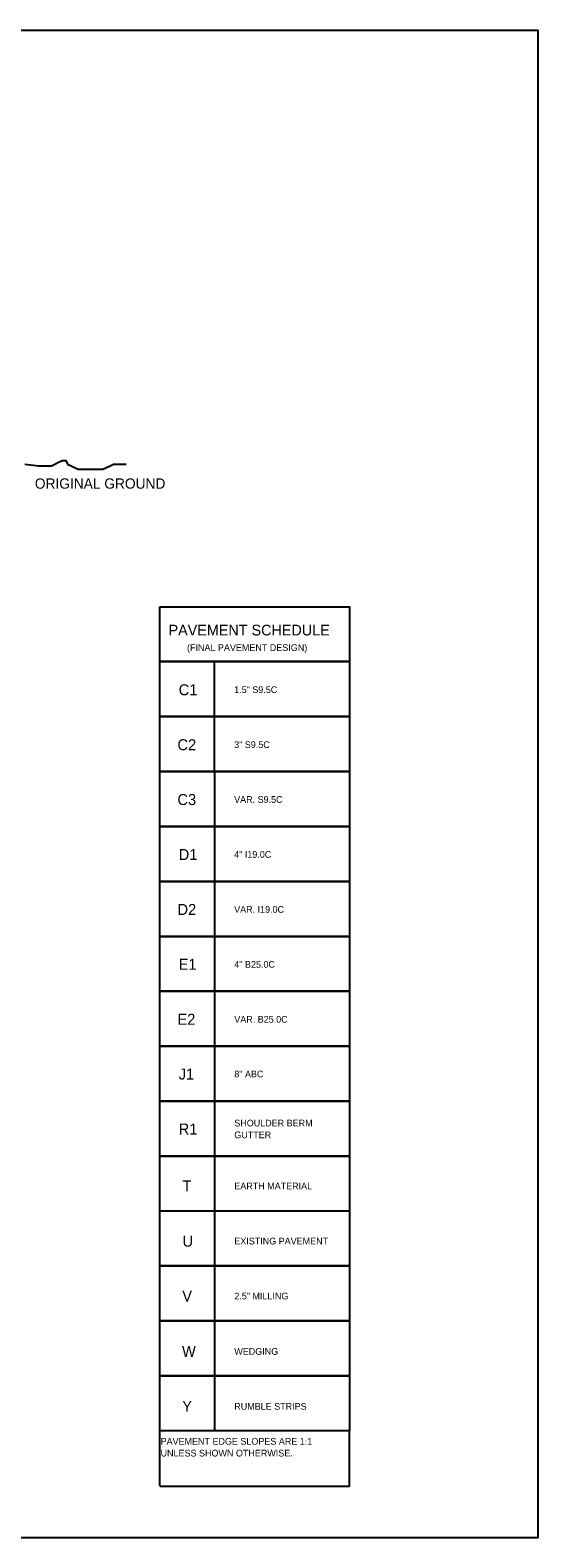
# Model space of a CAD drawing. Extents: x 1548135 to 1549339, y 868664 to 869085.
# Drawn here: x 1548268 to 1548305, y 868801.8 to 868911.8 of the extents above; entities that cross this region are included whole.
import ezdxf

# ---------------------------------------------------------------- set-up
doc = ezdxf.new("R2010")
doc.units = 0
for name, color, linetype in [('Default', 7, 'Continuous'), ('Prop Dimension', 7, 'Continuous'), ('Sheet_Data_Field_CELL', 7, 'Continuous'), ('Typical Hinge Slope Interstate CELL', 7, 'Continuous')]:
    doc.layers.add(name, color=color, linetype=linetype)

msp = doc.modelspace()

# ---------------------------------------------------------------- linework, layer by layer
at = {"layer": 'Default'}
msp.add_lwpolyline([(1548135.05, 868911.82), (1548305.05, 868911.82), (1548305.05, 868801.82), (1548135.05, 868801.82)], close=True, dxfattribs=at)
at = {"layer": 'Prop Dimension'}
msp.add_lwpolyline([(1548267.6, 868880.17), (1548268.63, 868880.04), (1548268.89, 868880.04), (1548269.28, 868880.04), (1548269.54, 868880.04), (1548269.8, 868880.17), (1548270.06, 868880.3), (1548270.32, 868880.43), (1548270.58, 868880.43), (1548270.71, 868880.17), (1548270.97, 868880.04), (1548271.23, 868879.91), (1548271.49, 868879.79), (1548271.75, 868879.79), (1548272.01, 868879.79), (1548272.27, 868879.79), (1548272.53, 868879.79), (1548272.78, 868879.79), (1548273.04, 868879.79), (1548273.3, 868879.79), (1548273.56, 868879.91), (1548273.82, 868880.04), (1548274.08, 868880.17), (1548274.47, 868880.17), (1548274.73, 868880.17), (1548274.99, 868880.17)], dxfattribs=at)
at = {"layer": 'Typical Hinge Slope Interstate CELL'}
for p, q in [((1548273.7, 868811.24), (1548273.7, 868811.24)), ((1548277.45, 868806.56), (1548277.45, 868809.66)), ((1548277.45, 868805.61), (1548277.45, 868809.62)), ((1548291.3, 868805.57), (1548291.3, 868809.62)), ((1548281.46, 868805.57), (1548277.45, 868805.57)), ((1548291.3, 868805.57), (1548281.46, 868805.57))]:
    msp.add_line(p, q, dxfattribs=at)
msp.add_lwpolyline([(1548277.45, 868869.75), (1548291.29, 868869.75), (1548291.29, 868865.75), (1548277.45, 868865.75)], close=True, dxfattribs=at)
for points in [[(1548281.45, 868861.74), (1548277.45, 868861.74), (1548277.45, 868865.75), (1548291.29, 868865.75), (1548291.29, 868861.74), (1548281.45, 868861.74), (1548281.45, 868865.75)], [(1548281.45, 868857.73), (1548277.45, 868857.73), (1548277.45, 868861.74), (1548291.29, 868861.74), (1548291.29, 868857.73), (1548281.45, 868857.73), (1548281.45, 868861.74)], [(1548281.46, 868853.72), (1548277.45, 868853.72), (1548277.45, 868857.73), (1548291.29, 868857.73), (1548291.29, 868853.72), (1548281.46, 868853.72), (1548281.46, 868857.73)], [(1548281.46, 868849.71), (1548277.45, 868849.71), (1548277.45, 868853.72), (1548291.29, 868853.72), (1548291.29, 868849.71), (1548281.46, 868849.71), (1548281.46, 868853.72)], [(1548281.46, 868845.7), (1548277.45, 868845.7), (1548277.45, 868849.71), (1548291.29, 868849.71), (1548291.29, 868845.7), (1548281.46, 868845.7), (1548281.46, 868849.71)], [(1548281.46, 868841.7), (1548277.45, 868841.7), (1548277.45, 868845.71), (1548291.3, 868845.71), (1548291.3, 868841.7), (1548281.46, 868841.7), (1548281.46, 868845.71)], [(1548281.46, 868841.69), (1548277.45, 868841.69), (1548277.45, 868845.7), (1548291.29, 868845.7), (1548291.29, 868841.69), (1548281.46, 868841.69), (1548281.46, 868845.7)], [(1548281.46, 868837.69), (1548277.45, 868837.69), (1548277.45, 868841.7), (1548291.3, 868841.7), (1548291.3, 868837.69), (1548281.46, 868837.69), (1548281.46, 868841.7)], [(1548281.46, 868833.69), (1548277.45, 868833.69), (1548277.45, 868837.7), (1548291.3, 868837.7), (1548291.3, 868833.69), (1548281.46, 868833.69), (1548281.46, 868837.7)], [(1548281.46, 868833.69), (1548277.45, 868833.69), (1548277.45, 868837.7), (1548291.3, 868837.7), (1548291.3, 868833.69), (1548281.46, 868833.69), (1548281.46, 868837.7)], [(1548281.46, 868829.68), (1548277.45, 868829.68), (1548277.45, 868833.69), (1548291.3, 868833.69), (1548291.3, 868829.68), (1548281.46, 868829.68), (1548281.46, 868833.69)], [(1548281.46, 868825.67), (1548277.45, 868825.67), (1548277.45, 868829.68), (1548291.3, 868829.68), (1548291.3, 868825.67), (1548281.46, 868825.67), (1548281.46, 868829.68)], [(1548281.46, 868821.67), (1548277.45, 868821.67), (1548277.45, 868825.68), (1548291.3, 868825.68), (1548291.3, 868821.67), (1548281.46, 868821.67), (1548281.46, 868825.68)], [(1548281.46, 868817.66), (1548277.45, 868817.66), (1548277.45, 868821.67), (1548291.3, 868821.67), (1548291.3, 868817.66), (1548281.46, 868817.66), (1548281.46, 868821.67)], [(1548281.46, 868813.65), (1548277.45, 868813.65), (1548277.45, 868817.66), (1548291.3, 868817.66), (1548291.3, 868813.65), (1548281.46, 868813.65), (1548281.46, 868817.66)], [(1548281.46, 868809.64), (1548277.45, 868809.64), (1548277.45, 868813.65), (1548291.3, 868813.65), (1548291.3, 868809.64), (1548281.46, 868809.64), (1548281.46, 868813.65)]]:
    msp.add_lwpolyline(points, dxfattribs=at)

# ---------------------------------------------------------------- texts
at = {"layer": 'Sheet_Data_Field_CELL'}
msp.add_text('ORIGINAL GROUND', height=0.75, dxfattribs=at).set_placement((1548268.33, 868878.37))
at = {"layer": 'Typical Hinge Slope Interstate CELL'}
for s, height, p in [('PAVEMENT SCHEDULE', 0.784, (1548278.09, 868867.66)), ('(FINAL PAVEMENT DESIGN)', 0.49, (1548279.44, 868866.53)), ('C1', 0.8, (1548278.83, 868863.3)), ('1.5" S9.5C', 0.49, (1548282.88, 868863.46)), ('C2', 0.8, (1548278.74, 868859.29)), ('3" S9.5C', 0.49, (1548282.88, 868859.45)), ('C3', 0.8, (1548278.74, 868855.29)), ('VAR. S9.5C', 0.49, (1548282.88, 868855.45)), ('D1', 0.8, (1548278.83, 868851.28)), ('4" I19.0C', 0.49, (1548282.88, 868851.44)), ('D2', 0.8, (1548278.74, 868847.27)), ('VAR. I19.0C', 0.49, (1548282.88, 868847.43)), ('E1', 0.8, (1548278.83, 868843.27)), ('4" B25.0C', 0.49, (1548282.89, 868843.42)), ('E2', 0.8, (1548278.74, 868839.26)), ('VAR. B25.0C', 0.49, (1548282.89, 868839.41)), ('J1', 0.8, (1548278.83, 868835.26)), ('8" ABC', 0.49, (1548282.89, 868835.42)), ('R1', 0.8, (1548278.83, 868831.25)), ('SHOULDER BERM', 0.49, (1548282.89, 868831.84)), ('GUTTER', 0.49, (1548282.89, 868830.98)), ('T', 0.8, (1548279.1, 868827.1)), ('EARTH MATERIAL', 0.49, (1548282.89, 868827.25)), ('U', 0.8, (1548279.11, 868823.07)), ('EXISTING PAVEMENT', 0.49, (1548282.89, 868823.23)), ('V', 0.8, (1548279.09, 868819.06)), ('2.5" MILLING', 0.49, (1548282.89, 868819.22)), ('W', 0.8, (1548279.07, 868815.03)), ('WEDGING', 0.49, (1548282.89, 868815.18)), ('Y', 0.8, (1548279.09, 868811.02)), ('RUMBLE STRIPS', 0.49, (1548282.89, 868811.17)), ('PAVEMENT EDGE SLOPES ARE 1:1', 0.49, (1548277.51, 868808.62)), ('UNLESS SHOWN OTHERWISE.', 0.49, (1548277.51, 868807.76))]:
    msp.add_text(s, height=height, dxfattribs=at).set_placement(p)

doc.saveas('drawing.dxf')
